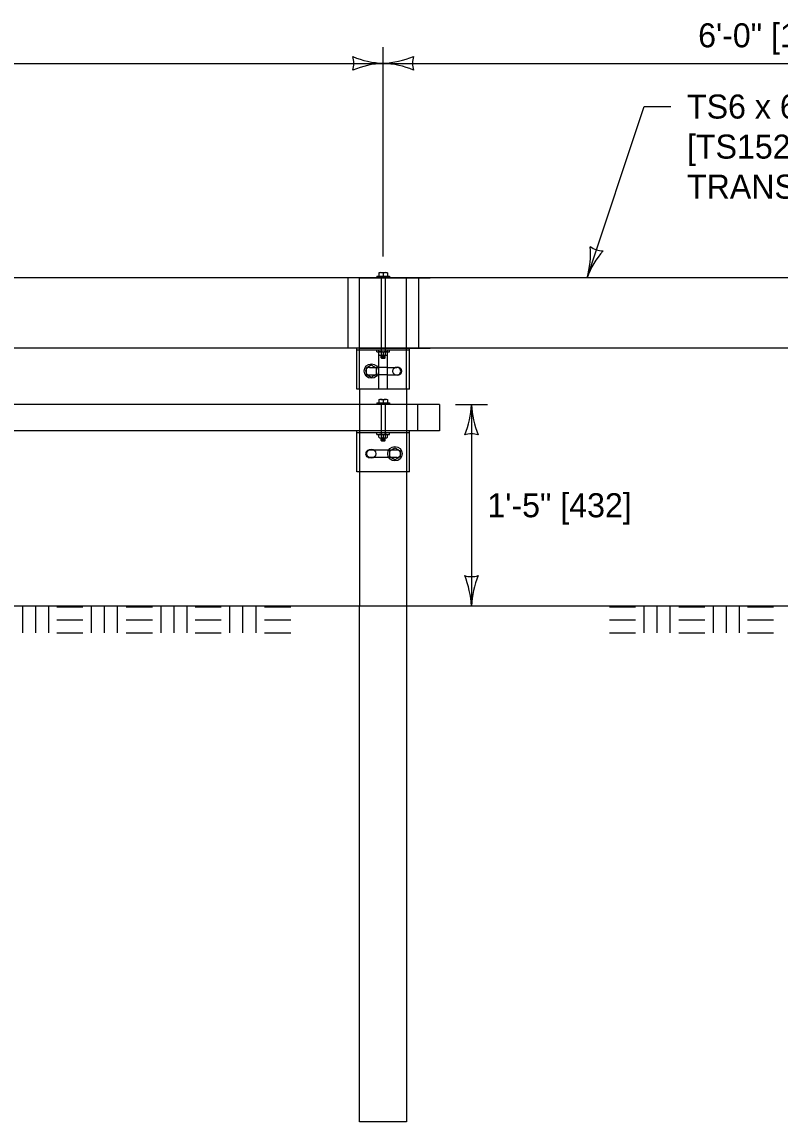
# Model space of a CAD drawing. Extents: x 49983 to 50021, y 49963.5 to 50011.4.
# Drawn here: x 50009.444 to 50011.337, y 49993.178 to 49995.925 of the extents above; entities that cross this region are included whole.
import ezdxf

# ---------------------------------------------------------------- set-up
doc = ezdxf.new("R2010")
doc.units = 0
for name, color, linetype in [('Level 1', 7, 'Continuous'), ('Level 10', 7, 'Continuous'), ('Level 2', 7, 'Continuous'), ('Level 3', 7, 'Continuous'), ('Level 4', 7, 'Continuous')]:
    doc.layers.add(name, color=color, linetype=linetype)

msp = doc.modelspace()

# ---------------------------------------------------------------- linework, layer by layer
at = {"layer": 'Level 1'}
for p, q in [((50013.5013, 49995.2862), (50005.468, 49995.2862)), ((50010.2876, 49995.2862), (50010.4633, 49995.2862)), ((50010.433, 49995.2862), (50010.3178, 49995.2862)), ((50010.3304, 49995.2899), (50010.3616, 49995.2899)), ((50010.3304, 49995.2899), (50010.3304, 49995.2862)), ((50010.3351, 49995.2981), (50010.3351, 49995.2899)), ((50010.3406, 49995.2988), (50010.3516, 49995.2988)), ((50010.3461, 49995.2981), (50010.3461, 49995.2899)), ((50010.3571, 49995.2981), (50010.3571, 49995.2899)), ((50010.3616, 49995.2899), (50010.3616, 49995.2862)), ((50013.5013, 49995.1105), (50005.468, 49995.1105)), ((50010.2803, 49995.008), (50010.2803, 49995.1105)), ((50010.2876, 49995.1105), (50010.4633, 49995.1105)), ((50010.3315, 49995.1105), (50010.4633, 49995.1105)), ((50010.412, 49995.008), (50010.412, 49995.1105)), ((50010.412, 49995.105), (50010.2803, 49995.105)), ((50010.3303, 49995.1014), (50010.3303, 49995.1051)), ((50010.3303, 49995.1014), (50010.3618, 49995.1014)), ((50010.3351, 49995.0942), (50010.3351, 49995.0997)), ((50010.3352, 49995.1014), (50010.3352, 49995.0998)), ((50010.3352, 49995.008), (50010.3352, 49995.0941)), ((50010.3406, 49995.0925), (50010.3517, 49995.0925)), ((50010.341, 49995.0864), (50010.341, 49995.0925)), ((50010.3513, 49995.0864), (50010.341, 49995.0864)), ((50010.341, 49995.0864), (50010.3421, 49995.0853)), ((50010.3421, 49995.0853), (50010.3503, 49995.0853)), ((50010.3425, 49995.091), (50010.3498, 49995.091)), ((50010.3425, 49995.09), (50010.3498, 49995.09)), ((50010.3425, 49995.089), (50010.3498, 49995.089)), ((50010.3425, 49995.0879), (50010.3498, 49995.0879)), ((50010.3462, 49995.0997), (50010.3462, 49995.0942)), ((50010.3513, 49995.0864), (50010.3503, 49995.0853)), ((50010.3513, 49995.0864), (50010.3513, 49995.0925)), ((50010.3571, 49995.1014), (50010.3571, 49995.0998)), ((50010.3571, 49995.008), (50010.3571, 49995.0941)), ((50010.3573, 49995.0942), (50010.3573, 49995.0997)), ((50010.3618, 49995.1014), (50010.3618, 49995.1051)), ((50010.3166, 49995.0678), (50010.3034, 49995.0601)), ((50010.3034, 49995.0601), (50010.3034, 49995.0453)), ((50010.3297, 49995.0601), (50010.3166, 49995.0678)), ((50010.3297, 49995.0453), (50010.3297, 49995.0601)), ((50010.3325, 49995.062), (50010.3352, 49995.062)), ((50010.3571, 49995.062), (50010.3804, 49995.062)), ((50010.3034, 49995.0453), (50010.3166, 49995.0382)), ((50010.3166, 49995.0382), (50010.3297, 49995.0453)), ((50010.3321, 49995.0437), (50010.3352, 49995.0437)), ((50010.3571, 49995.0437), (50010.3809, 49995.0437)), ((50010.412, 49995.008), (50010.2803, 49995.008)), ((50010.2874, 49995.008), (50010.2874, 49994.4663)), ((50010.4045, 49995.008), (50010.4045, 49994.4663)), ((50010.2874, 49994.9698), (50004.5699, 49994.9698)), ((50010.4865, 49994.9698), (50010.4045, 49994.9698)), ((50010.4865, 49994.9698), (50010.4865, 49994.9041)), ((50010.287, 49994.9041), (50005.1444, 49994.9041)), ((50010.2803, 49994.8016), (50010.2803, 49994.9041)), ((50010.4865, 49994.9041), (50010.4045, 49994.9041)), ((50010.412, 49994.8016), (50010.412, 49994.9041)), ((50010.2874, 49994.8016), (50010.2803, 49994.8016)), ((50010.412, 49994.8016), (50010.4045, 49994.8016)), ((50015.1755, 49994.4663), (50005.1046, 49994.4663)), ((50009.4461, 49994.3996), (50009.4461, 49994.4646)), ((50009.4785, 49994.3996), (50009.4785, 49994.4646)), ((50009.511, 49994.3996), (50009.511, 49994.4646)), ((50009.5313, 49994.4645), (50009.5963, 49994.4645)), ((50009.618, 49994.3995), (50009.618, 49994.4645)), ((50009.6505, 49994.3995), (50009.6505, 49994.4645)), ((50009.683, 49994.3995), (50009.683, 49994.4645)), ((50009.7046, 49994.4645), (50009.7697, 49994.4645)), ((50009.7914, 49994.3995), (50009.7914, 49994.4645)), ((50009.8238, 49994.3995), (50009.8238, 49994.4645)), ((50009.8563, 49994.3995), (50009.8563, 49994.4645)), ((50009.8769, 49994.4643), (50009.9419, 49994.4643)), ((50009.9636, 49994.3993), (50009.9636, 49994.4643)), ((50009.9961, 49994.3993), (50009.9961, 49994.4643)), ((50010.0286, 49994.3993), (50010.0286, 49994.4643)), ((50010.0502, 49994.4643), (50010.1153, 49994.4643)), ((50010.9111, 49994.4646), (50010.9761, 49994.4646)), ((50010.9978, 49994.3996), (50010.9978, 49994.4646)), ((50011.0303, 49994.3996), (50011.0303, 49994.4646)), ((50011.0628, 49994.3996), (50011.0628, 49994.4646)), ((50011.0844, 49994.4646), (50011.1495, 49994.4646)), ((50011.1712, 49994.3996), (50011.1712, 49994.4646)), ((50011.2036, 49994.3996), (50011.2036, 49994.4646)), ((50011.2361, 49994.3996), (50011.2361, 49994.4646)), ((50011.2564, 49994.4645), (50011.3214, 49994.4645)), ((50009.5313, 49994.432), (50009.5963, 49994.432)), ((50009.7046, 49994.432), (50009.7697, 49994.432)), ((50009.8769, 49994.4318), (50009.9419, 49994.4318)), ((50010.0502, 49994.4318), (50010.1153, 49994.4318)), ((50010.9111, 49994.4321), (50010.9761, 49994.4321)), ((50011.0844, 49994.4321), (50011.1495, 49994.4321)), ((50011.2564, 49994.432), (50011.3214, 49994.432)), ((50009.5313, 49994.3995), (50009.5963, 49994.3995)), ((50009.7046, 49994.3995), (50009.7697, 49994.3995)), ((50009.8769, 49994.3993), (50009.9419, 49994.3993)), ((50010.0502, 49994.3993), (50010.1153, 49994.3993)), ((50010.9111, 49994.3996), (50010.9761, 49994.3996)), ((50011.0844, 49994.3996), (50011.1495, 49994.3996)), ((50011.2564, 49994.3995), (50011.3214, 49994.3995))]:
    msp.add_line(p, q, dxfattribs=at)
for centre, radius in [((50010.3167, 49995.0531), 0.0181), ((50010.3167, 49994.8467), 0.011)]:
    msp.add_circle(centre, radius, dxfattribs=at)
for centre, radius, start, end in [((50010.3406, 49995.2757), 0.0231, 76.2307, 103.7693), ((50010.3516, 49995.2757), 0.0231, 76.2307, 103.7693), ((50010.3406, 49995.0916), 0.00981, 55.616, 124.384), ((50010.3406, 49995.1023), 0.00981, 235.616, 304.384), ((50010.3517, 49995.0916), 0.00981, 55.616, 124.384), ((50010.3517, 49995.1023), 0.00981, 235.616, 304.384), ((50010.3809, 49995.0528), 0.00916, 270, 93.2408)]:
    msp.add_arc(centre, radius, start, end, dxfattribs=at)
at = {"layer": 'Level 10'}
for p, q in [((50010.2874, 49995.008), (50010.2874, 49995.2862)), ((50010.341, 49995.2899), (50010.341, 49995.0925)), ((50010.3512, 49995.2899), (50010.3512, 49995.0925)), ((50010.4045, 49995.008), (50010.4045, 49995.2862)), ((50010.3352, 49995.1014), (50010.3352, 49995.105)), ((50010.3571, 49995.1014), (50010.3571, 49995.105)), ((50010.3119, 49995.062), (50010.3325, 49995.062)), ((50010.3571, 49995.062), (50010.3352, 49995.062)), ((50010.3114, 49995.0437), (50010.3321, 49995.0437)), ((50010.3571, 49995.0437), (50010.3352, 49995.0437)), ((50010.3304, 49994.9734), (50010.3616, 49994.9734)), ((50010.3304, 49994.9734), (50010.3304, 49994.9698)), ((50010.3351, 49994.9817), (50010.3351, 49994.9734)), ((50010.3406, 49994.9823), (50010.3516, 49994.9823)), ((50010.341, 49994.9734), (50010.341, 49994.8859)), ((50010.3461, 49994.9817), (50010.3461, 49994.9734)), ((50010.3512, 49994.9734), (50010.3512, 49994.8859)), ((50010.3571, 49994.9817), (50010.3571, 49994.9734)), ((50010.3616, 49994.9734), (50010.3616, 49994.9698)), ((50010.4045, 49994.9698), (50010.2874, 49994.9698)), ((50010.4322, 49994.9698), (50010.4322, 49994.9041)), ((50010.2874, 49994.8986), (50010.2803, 49994.8986)), ((50010.4045, 49994.9041), (50010.2874, 49994.9041)), ((50010.4045, 49994.8986), (50010.2874, 49994.8986)), ((50010.3303, 49994.8949), (50010.3303, 49994.8986)), ((50010.3303, 49994.8949), (50010.3618, 49994.8949)), ((50010.3351, 49994.8876), (50010.3351, 49994.8932)), ((50010.3462, 49994.8932), (50010.3462, 49994.8876)), ((50010.3573, 49994.8876), (50010.3573, 49994.8932)), ((50010.3618, 49994.8949), (50010.3618, 49994.8986)), ((50010.412, 49994.8986), (50010.4045, 49994.8986)), ((50010.3406, 49994.8859), (50010.3517, 49994.8859)), ((50010.341, 49994.8798), (50010.341, 49994.8859)), ((50010.3513, 49994.8798), (50010.341, 49994.8798)), ((50010.341, 49994.8798), (50010.3421, 49994.8788)), ((50010.3421, 49994.8788), (50010.3503, 49994.8788)), ((50010.3425, 49994.8845), (50010.3498, 49994.8845)), ((50010.3425, 49994.8835), (50010.3498, 49994.8835)), ((50010.3425, 49994.8824), (50010.3498, 49994.8824)), ((50010.3425, 49994.8814), (50010.3498, 49994.8814)), ((50010.3513, 49994.8798), (50010.3503, 49994.8788)), ((50010.3513, 49994.8798), (50010.3513, 49994.8859)), ((50010.3352, 49994.8372), (50010.3114, 49994.8372)), ((50010.3352, 49994.8555), (50010.3119, 49994.8555)), ((50010.3571, 49994.8555), (50010.3352, 49994.8555)), ((50010.3571, 49994.8372), (50010.3352, 49994.8372)), ((50010.3598, 49994.8555), (50010.3571, 49994.8555)), ((50010.3601, 49994.8372), (50010.3571, 49994.8372)), ((50010.3804, 49994.8555), (50010.3598, 49994.8555)), ((50010.3809, 49994.8372), (50010.3601, 49994.8372)), ((50010.3626, 49994.8537), (50010.3757, 49994.8613)), ((50010.3626, 49994.8389), (50010.3626, 49994.8537)), ((50010.3757, 49994.8318), (50010.3626, 49994.8389)), ((50010.3757, 49994.8613), (50010.3888, 49994.8537)), ((50010.3888, 49994.8389), (50010.3757, 49994.8318)), ((50010.3888, 49994.8537), (50010.3888, 49994.8389)), ((50010.4045, 49994.8016), (50010.2874, 49994.8016))]:
    msp.add_line(p, q, dxfattribs=at)
for centre, radius in [((50010.3809, 49995.0528), 0.011), ((50010.3756, 49994.8467), 0.0181)]:
    msp.add_circle(centre, radius, dxfattribs=at)
for centre, radius, start, end in [((50010.3114, 49995.0528), 0.00916, 86.7592, 270), ((50010.3406, 49994.9592), 0.0231, 76.2307, 103.7693), ((50010.3516, 49994.9592), 0.0231, 76.2307, 103.7693), ((50010.3406, 49994.8851), 0.00981, 55.616, 124.384), ((50010.3517, 49994.8851), 0.00981, 55.616, 124.384), ((50010.3406, 49994.8957), 0.00981, 235.616, 304.384), ((50010.3517, 49994.8957), 0.00981, 235.616, 304.384), ((50010.3114, 49994.8464), 0.00916, 86.7592, 270), ((50010.3809, 49994.8464), 0.00916, 270, 93.2408)]:
    msp.add_arc(centre, radius, start, end, dxfattribs=at)
at = {"layer": 'Level 3'}
for p, q in [((50010.3461, 49995.3388), (50010.3461, 49995.8615)), ((50007.535, 49995.8215), (50010.3461, 49995.8215)), ((50010.3461, 49995.8215), (50012.4546, 49995.8215)), ((50010.8554, 49995.2862), (50010.9977, 49995.7136)), ((50010.9977, 49995.7136), (50011.065, 49995.7136)), ((50010.5265, 49994.9698), (50010.6065, 49994.9698)), ((50010.5665, 49994.9698), (50010.5665, 49994.4663))]:
    msp.add_line(p, q, dxfattribs=at)
for centre, radius, start, end in [((50010.3553, 49996.0437), 0.2223, 247.456, 267.6395), ((50010.2179, 49995.8215), 0.0548, 342.1388, 17.8612), ((50010.3346, 49996.0543), 0.233, 272.8273, 292.0772), ((50010.4744, 49995.8215), 0.0548, 162.1388, 197.8612), ((50010.3576, 49995.5888), 0.233, 92.8273, 112.0772), ((50010.337, 49995.5994), 0.2223, 67.456, 87.6395), ((50010.631, 49995.3488), 0.233, 344.4135, 3.6633), ((50010.8959, 49995.4079), 0.0548, 233.725, 269.4473), ((50011.0633, 49995.2074), 0.2223, 139.0422, 159.2257), ((50010.3444, 49994.9789), 0.2223, 337.456, 357.6395), ((50010.7993, 49994.9812), 0.233, 182.8273, 202.0772), ((50010.5665, 49994.8415), 0.0548, 72.1388, 107.8612), ((50010.5665, 49994.5945), 0.0548, 252.1388, 287.8612), ((50010.3338, 49994.4548), 0.233, 2.8273, 22.0772), ((50010.7887, 49994.4572), 0.2223, 157.456, 177.6395)]:
    msp.add_arc(centre, radius, start, end, dxfattribs=at)
at = {"layer": 'Level 4'}
for p, q in [((50010.2583, 49995.2862), (50010.2583, 49995.1105)), ((50010.434, 49995.2862), (50010.434, 49995.1105)), ((50010.2874, 49993.1779), (50010.2874, 49994.4663)), ((50010.4045, 49994.4663), (50010.4045, 49993.1779)), ((50010.4045, 49993.1779), (50010.2874, 49993.1779))]:
    msp.add_line(p, q, dxfattribs=at)

# ---------------------------------------------------------------- texts
at = {"layer": 'Level 2'}
for s, p in [('6\'-0" [1830]', (50011.1328, 49995.8615)), ('TS6 x 6 x 3/16', (50011.105, 49995.6836)), ('[TS152 x 152 x 4.8]', (50011.105, 49995.5836)), ('TRANSITION RAIL*', (50011.105, 49995.4836)), ('1\'-5" [432]', (50010.6065, 49994.688))]:
    msp.add_text(s, height=0.06, dxfattribs=at).set_placement(p)

doc.saveas('drawing.dxf')
